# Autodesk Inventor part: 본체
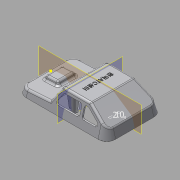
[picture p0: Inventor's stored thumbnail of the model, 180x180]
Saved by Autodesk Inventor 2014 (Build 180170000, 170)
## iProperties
Created: 2015-05
Part Number: 본체
Material: ABS 플라스틱
Document SubType Name: Modeling
Designer: Administrator
Density: 1.06 g/cm^3
Appearance: 매끄러움 - 흰색
Mass: 32.0436 g
Surface Area: 312.885 cm^2
Volume: 30.2298 cm^3
Author: Administrator
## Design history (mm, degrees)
sketch "스케치2"
  geometry: L1 (-49, -38)-(49, -38); L2 (61, -26)-(61, 26); L3 (49, 38)-(-49, 38); L4 (-61, 26)-(-61, -26); L5 (-61, -38)-(61, 38); L6 (61, -38)-(-61, 38); A1 r 12 centre (-49, 26) between (-49, 38) and (-61, 26); A2 r 12 centre (-49, -26) between (-61, -26) and (-49, -38); A3 r 12 centre (49, -26) between (49, -38) and (61, -26); A4 r 12 centre (49, 26) between (61, 26) and (49, 38); 1 further point
  constraints: 12 end point, 8 point on circle, 8 point on line, 8 tangent, 4 centre point, 3 equal radius, 2 midpoint, 2 parallel, 1 horizontal, 1 perpendicular
  dimensions: "d1" = 122 distance of L5.end L6.end; "d2" = 76 distance of L6.start L5.end; "d3" = 12 radius of A1
extrude "돌출1" new body sketch "스케치2" distance "d4" = 30; taper "d5" = -15 deg
sketch "스케치3"
  geometry: L1 (-61, 0)-(-49, 0) reference; L2 (49, 30)-(-49, 30) reference; L3 (-61, 30)-(-31, 30); L4 (-31, 30)-(-61, 10); L5 (-61, 10)-(-61, 30); 2 further points
  constraints: 6 end point, 1 horizontal, 1 midpoint, 1 perpendicular, 1 point on line, 1 vertical alignment
  dimensions: "d6" = 20 distance of L4.end L3.start; "d7" = 30 distance of L3.start L3.end
extrude "돌출2" cut sketch "스케치3" stored distance "d8" = 30; taper "d9" = 0 deg
sketch "스케치4"
  geometry: L1 (49, 0)-(61, 0) reference; L2 (61, 0)-(61, 8); L3 (61, 0)-(52.962, 30) reference; L4 (49, 30)-(-31, 30) reference; L5 (58.826, 8.114)-(19, 10.201); L6 (19, 10.201)-(6.628, 30); L7 (58.826, 8.114)-(58.826, 30); L8 (58.826, 30)-(6.628, 30); L9 (58.826, 8.114)-(61, 8); 1 further point
  constraints: 12 end point, 2 collinear, 2 perpendicular, 2 point on line
  dimensions: "d11" = 42 horizontal distance of L5.end L1.end; "d12" = 125 deg angle of L6 L5; "d13" = 3 deg angle of L5 L1; "d14" = 8 distance of L1.end L2.end
extrude "돌출3" cut sketch "스케치4" stored distance "d15" = 30; taper "d16" = 0 deg
sketch "스케치5"
  geometry: L1 (49, 38)-(-49, 38) reference; L2 (-61, 26)-(-61, -26) reference; L3 (-49, -38)-(49, -38) reference; L4 (61, -26)-(61, 26) reference; A1 r 12 centre (-49, 26) between (-49, 38) and (-61, 26) reference; A2 r 12 centre (-49, -26) between (-61, -26) and (-49, -38) reference; A3 r 12 centre (49, -26) between (49, -38) and (61, -26) reference; A4 r 12 centre (49, 26) between (61, 26) and (49, 38) reference; 1 further point
sketch "스케치6"
  geometry: L1 (-39.881, 9.267)-(-39.881, 61.267) reference; L2 (-31.476, 48.267)-(-11.476, 48.267); L3 (-11.476, 48.267)-(-11.476, 22.267); L4 (-11.476, 22.267)-(-31.476, 22.267); L5 (-31.476, 22.267)-(-31.476, 48.267); L6 (-31.476, 48.267)-(-11.476, 22.267); L7 (-11.476, 48.267)-(-31.476, 22.267); L8 (-42.476, 9.267)-(-42.476, 61.267) reference; 4 further points
  constraints: 12 end point, 4 midpoint, 2 parallel, 1 horizontal, 1 horizontal alignment, 1 perpendicular
  dimensions: "d17" = 20 distance of L3.end L4.end; "d18" = 26 distance of L2.end L3.end; "d19" = 11 distance between parallel lines of L8 L5
extrude "돌출4" join sketch "스케치6" distance "d20" = 5; taper "d21" = -20 deg
fillet "모깎기1" dims "d22" = 3
fillet "모깎기2" dims "d23" = 3
sketch "스케치7"
  geometry: 1 further point
sketch "스케치8"
  geometry: L1 (-50.664, 16.891)-(-31.756, 29.496) reference; L2 (-61, 0)-(-58.03, 11.082) reference; 1 further point
feature "쉘1" dims "d24" = 2
sketch "스케치9"
  geometry: L1 (-58.929, -26)-(-58.929, 26) reference; L2 (-49, 35.929)-(49, 35.929) reference; L3 (58.929, 26)-(58.929, -26) reference; L4 (49, -35.929)-(-49, -35.929) reference; L5 (49, 35.882)-(-49, 35.882); L6 (-58.882, 26)-(-58.882, -26); L7 (-49, -35.882)-(49, -35.882); L8 (58.882, -26)-(58.882, 26); L9 (49, 36.929)-(-49, 36.929); L10 (-59.929, 26)-(-59.929, -26); L11 (-49, -36.929)-(49, -36.929); L12 (59.929, -26)-(59.929, 26); A1 r 9.929 centre (-49, -26) between (-58.929, -26) and (-49, -35.929) reference; A2 r 9.929 centre (-49, 26) between (-49, 35.929) and (-58.929, 26) reference; A3 r 9.929 centre (49, 26) between (58.929, 26) and (49, 35.929) reference; A4 r 9.929 centre (49, -26) between (49, -35.929) and (58.929, -26) reference; A5 r 9.882 centre (-49, 26) between (-49, 35.882) and (-58.882, 26); A6 r 9.882 centre (-49, -26) between (-58.882, -26) and (-49, -35.882); A7 r 9.882 centre (49, -26) between (49, -35.882) and (58.882, -26); A8 r 9.882 centre (49, 26) between (58.882, 26) and (49, 35.882); A9 r 10.929 centre (-49, 26) between (-49, 36.929) and (-59.929, 26); A10 r 10.929 centre (-49, -26) between (-59.929, -26) and (-49, -36.929); A11 r 10.929 centre (49, -26) between (49, -36.929) and (59.929, -26); A12 r 10.929 centre (49, 26) between (59.929, 26) and (49, 36.929); 1 further point
  constraints: 16 end point, 16 point on circle, 8 centre point, 14 other
  dimensions: "d25" = 1 distance between parallel lines of L9 L2
extrude "돌출5" join sketch "스케치9" distance "d26" = 1; taper "d27" = 0 deg
sketch "스케치10"
  geometry: L1 (4.965, 30)-(-30.092, 30) reference; L2 (19, 10.201)-(7.51, 28.59) reference; L3 (-30.646, 27.832)-(-49.555, 15.226) reference; L4 (10.362, 14.59)-(4.738, 23.59); L5 (-30.242, 24.496)-(-43.742, 15.496); L6 (-31.756, 29.496)-(-50.664, 16.891) reference; L7 (-42.078, 10)-(-26.986, 10); L8 (-23.986, 13)-(-23.986, 22); L9 (-20.77, 22)-(-20.77, 13); L10 (-17.77, 10)-(7.818, 10); L11 (2.194, 25)-(-17.77, 25); L12 (-26.986, 25)-(-28.578, 25); A1 r 3 centre (-28.578, 22) between (-28.578, 25) and (-30.242, 24.496); A2 r 3 centre (-42.078, 13) between (-43.742, 15.496) and (-42.078, 10); A3 r 3 centre (-26.986, 13) between (-26.986, 10) and (-23.986, 13); A4 r 3 centre (-26.986, 22) between (-23.986, 22) and (-26.986, 25); A5 r 3 centre (-17.77, 22) between (-17.77, 25) and (-20.77, 22); A6 r 3 centre (-17.77, 13) between (-20.77, 13) and (-17.77, 10); A7 r 3 centre (2.194, 22) between (4.738, 23.59) and (2.194, 25); A8 r 3 centre (7.818, 13) between (7.818, 10) and (10.362, 14.59); 7 further points
  constraints: 16 end point, 16 point on circle, 16 tangent, 12 point on line, 8 centre point, 7 equal radius, 7 parallel, 2 perpendicular
  dimensions: "d29" = 5 distance between parallel lines of L2 L4; "d30" = 5 distance between parallel lines of L6 L5; "d31" = 28 distance of point (-51.986, 10) point (-23.986, 10); "d32" = 15 distance of point (-23.986, 10) point (-23.986, 25); "d33" = 15 distance of point (-20.77, 25) point (-20.77, 10); "d34" = 5 distance between parallel lines of L1 L11; "d35" = 5 distance between parallel lines of L1 L12; "d36" = 34 distance of point (-20.77, 10) point (13.23, 10); "d37" = 3 radius of A1
extrude "돌출6" cut sketch "스케치10" stored distance "d38" = 1; taper "d39" = 0 deg
node "작업 평면1"
sketch "스케치11"
  geometry: A1 r 4 centre (-10, 0) between (-6, 0) and (-14, 0); A2 r 4 centre (10, 0) between (14, 0) and (6, 0); A3 r 4 centre (21, 0) between (25, 0) and (17, 0); A4 r 4 centre (-21, 0) between (-17, 0) and (-25, 0); 3 further points
  constraints: 8 point on circle, 4 centre point, 13 other
  dimensions: "d41" = 8 diameter of A1; "d42" = 8 diameter of A2; "d43" = 8 diameter of A4; "d44" = 8 diameter of A3; "d45" = 20 distance of A2.centre A1.centre; "d46" = 11 distance of A1.centre A4.centre; "d47" = 11 distance of A3.centre A2.centre; "d48" = 10 distance of A2.centre point (0, 0)
extrude "돌출7" join sketch "스케치11" stored distance "d49" = 2; taper "d50" = 0 deg
chamfer "모따기1" distance "d51" = 1; stored, may be unused: second distance "d52" = 2, angle "d53" = 45 deg
sketch "스케치12"
  geometry: C1 r 3 at (0, 22); C2 r 3 at (0, -22); C3 r 3 at (40, 0); C4 r 3 at (-40, 0); 1 further point
  constraints: 4 centre point, 2 horizontal alignment, 2 vertical alignment
  dimensions: "d54" = 6 diameter of C4; "d55" = 6 diameter of C1; "d56" = 6 diameter of C3; "d57" = 6 diameter of C2; "d58" = 44 distance of C2.centre C1.centre; "d59" = 22 distance of point (0, 0) C1.centre; "d60" = 40 distance of C4.centre point (0, 0); "d61" = 40 distance of C3.centre point (0, 0)
extrude "돌출8" join sketch "스케치12" stored distance "d62" = 1; taper "d63" = 2 deg
sketch "스케치13"
  geometry: L1 (-5, -1)-(5, -1); L2 (5, -1)-(5, 1); L3 (5, 1)-(-5, 1); L4 (-5, 1)-(-5, -1); L5 (-5, -1)-(5, 1); L6 (5, -1)-(-5, 1); L7 (-5, 43)-(5, 43); L8 (5, 43)-(5, 45); L9 (5, 45)-(-5, 45); L10 (-5, 45)-(-5, 43); L11 (-5, 43)-(5, 45); L12 (5, 43)-(-5, 45); L13 (35, 21)-(45, 21); L14 (45, 21)-(45, 23); L15 (45, 23)-(35, 23); L16 (35, 23)-(35, 21); L17 (35, 21)-(45, 23); L18 (45, 21)-(35, 23); L19 (-45, 21)-(-35, 21); L20 (-35, 21)-(-35, 23); L21 (-35, 23)-(-45, 23); L22 (-45, 23)-(-45, 21); L23 (-45, 21)-(-35, 23); L24 (-35, 21)-(-45, 23); C1 r 3 at (0, 0) reference; C2 r 3 at (-40, 22) reference; C3 r 3 at (0, 44) reference; C4 r 3 at (40, 22) reference; 1 further point
  constraints: 48 end point, 8 midpoint, 8 parallel, 4 horizontal, 4 perpendicular
  dimensions: "d64" = 2 distance of L19.end L20.end; "d65" = 10 distance of L19.start L19.end; "d66" = 10 distance of L7.start L7.end; "d67" = 10 distance of L2.end L3.end; "d68" = 10 distance of L14.end L15.end; "d69" = 2 distance of L15.end L13.start; "d70" = 2 distance of L7.end L8.end; "d71" = 2 distance of L1.end L2.end
extrude "돌출9" join sketch "스케치13" stored distance "d72" = 0; taper "d73" = 0 deg
sketch "스케치14"
  geometry: L1 (2.172, 0)-(2.172, 28) reference; L2 (-7.828, 0)-(-7.828, 27.999) reference; L3 (-7.794, 28)-(27.263, 28) reference; L4 (2.172, 0)-(7.109, 28); L5 (2.172, 0)-(2.172, 28); L6 (7.109, 28)-(2.172, 28); 1 further point
  constraints: 6 end point, 2 collinear, 1 point on line
  dimensions: "d74" = 10 deg angle of L4 L5
extrude "돌출10" join sketch "스케치14" stored distance "d75" = 1; taper "d76" = 0 deg
sketch "스케치15"
  geometry: L1 (-4.519, -2.57)-(-2.913, 0) reference; L2 (-4.519, -2.57)-(-4.972, 0) reference; L3 (-4.972, 0)-(-2.913, 0) reference; 1 further point
extrude "돌출11" cut sketch "스케치15" stored distance "d77" = 1; taper "d78" = 0 deg
sketch "스케치16"
  geometry: L1 (2.172, 0)-(2.172, 12.367) reference; L2 (2.172, 0)-(6.673, 12.367); L3 (6.673, 12.367)-(2.172, 12.367); L4 (2.172, 0)-(2.172, 12.367); 1 further point
  constraints: 6 end point, 1 collinear, 1 perpendicular
  dimensions: "d79" = 20 deg angle of L2 L4
extrude "돌출12" join sketch "스케치16" stored distance "d80" = 1; taper "d81" = 0 deg
sketch "스케치17"
  geometry: L1 (6.178, 11.009)-(6.673, 12.367) reference; L2 (6.673, 12.367)-(5.537, 12.367) reference; L3 (5.89, 11.534)-(5.537, 12.367) reference; A1 r 3 centre (8.652, 12.706) between (5.89, 11.534) and (6.178, 11.009) reference; 1 further point
extrude "돌출13" cut sketch "스케치17" stored distance "d82" = 1; taper "d83" = 0 deg
sketch "스케치18"
  geometry: L1 (0, 0)-(0, 11.843) reference; L2 (-2.906, 9.978)-(-2.579, 11.049) reference; L3 (-1.675, 11.755)-(10.467, 12.391) reference; L4 (0, 0)-(-3.295, 9.052); A1 r 1 centre (-1.623, 10.756) between (-1.675, 11.755) and (-2.579, 11.049) reference; A2 r 5 centre (-7.688, 11.44) between (-7.426, 6.447) and (-2.906, 9.978) reference; 1 further point
  constraints: 2 end point, 1 point on circle
  dimensions: "d84" = 20 deg angle of L1 L4
extrude "돌출14" join sketch "스케치18" stored distance "d85" = 1; taper "d86" = 0 deg
sketch "스케치19"
  geometry: L1 (0, 0)-(0, 24.93) reference; L2 (-4.354, 27.832)-(14.555, 15.226) reference; L3 (-39.965, 28)-(-4.908, 28) reference; L4 (0, 0)-(-5.745, 28); A1 r 1 centre (-4.908, 27) between (-4.354, 27.832) and (-4.908, 28) reference; 1 further point
  constraints: 2 end point, 1 point on line
  dimensions: "d87" = 11.5941 deg angle of L1 L4
extrude "돌출15" join sketch "스케치19" stored distance "d88" = 1; taper "d89" = 0 deg
sketch "스케치20"
  geometry: L1 (2.172, 0)-(2.172, 18.263) reference; L2 (-12.182, 27.832)-(6.726, 15.226) reference; L3 (2.172, 0)-(7.521, 14.697); L4 (6.726, 15.226)-(7.521, 14.697); 1 further point
  constraints: 4 end point, 1 collinear, 1 point on line
  dimensions: "d90" = 20 deg angle of L3 L1
extrude "돌출16" join sketch "스케치20" stored distance "d91" = 1; taper "d92" = 0 deg
sketch "스케치21"
  geometry: L1 (-2.828, 23)-(-5, 23) reference; L2 (-5, 23)-(-5, 21) reference; L3 (-5, 21)-(-2.828, 21) reference; L4 (2.828, 21)-(5, 21) reference; L5 (5, 21)-(5, 23) reference; L6 (5, 23)-(2.828, 23) reference; L7 (-42.828, 1)-(-45, 1) reference; L8 (-45, 1)-(-45, -1) reference; L9 (-45, -1)-(-42.828, -1) reference; L10 (-37.172, -1)-(-35, -1) reference; L11 (-35, -1)-(-35, 1) reference; L12 (-35, 1)-(-37.172, 1) reference; L13 (37.172, 1)-(35, 1) reference; L14 (35, 1)-(35, -1) reference; L15 (35, -1)-(37.172, -1) reference; L16 (42.828, -1)-(45, -1) reference; L17 (45, -1)-(45, 1) reference; L18 (45, 1)-(42.828, 1) reference; C1 r 3 at (0, -22); C2 r 3 at (0, 22); C3 r 3 at (40, 0); A1 r 3 centre (0, -22) between (2.828, -21) and (-2.828, -21) reference; A2 r 3 centre (0, -22) between (-2.828, -23) and (2.828, -23) reference; A3 r 3 centre (0, 22) between (2.828, 23) and (-2.828, 23) reference; A4 r 3 centre (0, 22) between (-2.828, 21) and (2.828, 21) reference; A5 r 3 centre (-40, 0) between (-37.172, 1) and (-42.828, 1) reference; A6 r 3 centre (-40, 0) between (-42.828, -1) and (-37.172, -1) reference; A7 r 3 centre (40, 0) between (42.828, 1) and (37.172, 1) reference; A8 r 3 centre (40, 0) between (37.172, -1) and (42.828, -1) reference; 1 further point
  constraints: 3 centre point, 3 coincident, 3 concentric
  node "투영된 루프4"
  node "투영된 루프5"
  node "투영된 루프6"
sketch "스케치22"
  geometry: L1 (-42.828, 1)-(-45, 1) reference; L2 (-45, 1)-(-45, -1) reference; L3 (-45, -1)-(-42.828, -1) reference; L4 (-37.172, -1)-(-35, -1) reference; L5 (-35, -1)-(-35, 1) reference; L6 (-35, 1)-(-37.172, 1) reference; A1 r 3 centre (-40, 0) between (-37.172, 1) and (-42.828, 1) reference; A2 r 3 centre (-40, 0) between (-42.828, -1) and (-37.172, -1) reference; 1 further point
sketch "스케치23"
  geometry: L1 (-42.828, 1)-(-45, 1) reference; L2 (-45, 1)-(-45, -1) reference; L3 (-45, -1)-(-42.828, -1) reference; L4 (-37.172, -1)-(-35, -1) reference; L5 (-35, -1)-(-35, 1) reference; L6 (-35, 1)-(-37.172, 1) reference; C1 r 3 at (-40, 0); A1 r 3 centre (-40, 0) between (-37.172, 1) and (-42.828, 1) reference; A2 r 3 centre (-40, 0) between (-42.828, -1) and (-37.172, -1) reference; 1 further point
  constraints: 1 centre point, 1 coincident, 1 concentric
sketch "스케치24"
  geometry: L1 (2.172, 0)-(0, 0) reference; L2 (2.172, 0)-(7.109, 28) reference; L3 (-7.828, 0)-(-11.793, 22.486) reference; L4 (-8.181, 2)-(2.524, 2); L5 (0, 0)-(-5.657, 0) reference; L6 (-5.657, 0)-(-5.657, 2); L7 (0, 0)-(0, 2); L8 (-8.181, 2)-(-7.828, 0); L9 (-5.657, 0)-(-7.828, 0); L10 (0, 0)-(2.172, 0); L11 (2.524, 2)-(2.172, 0); 1 further point
  constraints: 14 end point, 4 point on line, 3 collinear, 2 parallel, 2 perpendicular
  dimensions: "d93" = 2 distance between parallel lines of L5 L4
extrude "돌출17" cut sketch "스케치24" stored distance "d94" = 2; taper "d95" = 0 deg
sketch "스케치25"
  geometry: L1 (-1.675, 11.755)-(1.733, 11.933) reference; L2 (-2.906, 9.978)-(-2.579, 11.049) reference; L3 (-3.295, 9.052)-(0, 0) reference; L4 (2.172, 0)-(0, 0) reference; L5 (10, 0)-(13.239, 8.899) reference; L6 (-0.728, 2)-(10.728, 2); L7 (7.828, 0)-(2.172, 0) reference; L8 (-0.728, 2)-(0, 0); L9 (2.172, 0)-(2.098, 2); L10 (8.28, 12.277)-(10, 12.367) reference; L11 (10, 0)-(7.828, 0) reference; L12 (10, 0)-(13.239, 8.899) reference; L13 (11.44, 11.783)-(11.878, 10.753) reference; L14 (10.746, 12.367)-(10, 12.367) reference; L15 (0, 0)-(2.172, 0); A1 r 1 centre (-1.623, 10.756) between (-1.675, 11.755) and (-2.579, 11.049) reference; A2 r 5 centre (-7.688, 11.44) between (-3.295, 9.052) and (-2.906, 9.978) reference; A3 r 5 centre (16.48, 12.706) between (11.878, 10.753) and (13.239, 8.899) reference; A4 r 1 centre (10.52, 11.393) between (11.44, 11.783) and (10.746, 12.367) reference; 1 further point
  constraints: 8 end point, 3 point on line, 2 collinear, 1 parallel, 3 other
  dimensions: "d96" = 2 distance between parallel lines of L7 L6
sketch "스케치26"
  geometry: L1 (-1.675, 11.755)-(1.733, 11.933) reference; L2 (-2.906, 9.978)-(-2.579, 11.049) reference; L3 (-3.295, 9.052)-(0, 0) reference; L4 (2.172, 0)-(0, 0) reference; L5 (8.28, 12.277)-(10, 12.367) reference; L6 (10, 0)-(7.828, 0) reference; L7 (10, 0)-(13.239, 8.899) reference; L8 (11.44, 11.783)-(11.878, 10.753) reference; L9 (10.746, 12.367)-(10, 12.367) reference; A1 r 1 centre (-1.623, 10.756) between (-1.675, 11.755) and (-2.579, 11.049) reference; A2 r 5 centre (-7.688, 11.44) between (-3.295, 9.052) and (-2.906, 9.978) reference; A3 r 5 centre (16.48, 12.706) between (11.878, 10.753) and (13.239, 8.899) reference; A4 r 1 centre (10.52, 11.393) between (11.44, 11.783) and (10.746, 12.367) reference; 1 further point
  constraints: 2 other
sketch "스케치27"
  geometry: L1 (-1.675, 11.755)-(1.733, 11.933) reference; L2 (-2.906, 9.978)-(-2.579, 11.049) reference; L3 (-3.295, 9.052)-(0, 0) reference; L4 (2.172, 0)-(0, 0) reference; L5 (-3.295, 9.052)-(0, 0) reference; L6 (2.172, 0)-(0, 0) reference; L7 (2.172, 0)-(2.098, 2) reference; L8 (-0.728, 2)-(0, 0); L9 (2.172, 0)-(0, 0); L10 (2.172, 0)-(2.098, 2); A1 r 1 centre (-1.623, 10.756) between (-1.675, 11.755) and (-2.579, 11.049) reference; A2 r 5 centre (-7.688, 11.44) between (-3.295, 9.052) and (-2.906, 9.978) reference; 2 further points
  constraints: 6 end point, 3 collinear, 1 point on line, 1 other
sketch "스케치28"
  geometry: L1 (-5.745, 28)-(0, 0) reference; L2 (2.172, 0)-(0, 0) reference; L3 (-0.41, 2)-(2.098, 2); 2 further points
  constraints: 2 end point, 1 parallel, 1 point on line, 2 other
  dimensions: "d97" = 2 distance between parallel lines of L3 L2
extrude "돌출18" cut sketch "스케치28" stored distance "d98" = 2; taper "d99" = 0 deg
sketch "스케치29"
  geometry: L1 (2.172, 0)-(0, 0) reference; L2 (2.172, 0)-(7.521, 14.697) reference; L3 (0.074, 2)-(2.9, 2); 2 further points
  constraints: 2 end point, 1 parallel, 1 point on line, 2 other
  dimensions: "d100" = 2 distance between parallel lines of L1 L3
extrude "돌출19" cut sketch "스케치29" stored distance "d101" = 2; taper "d102" = 0 deg
sketch "스케치30"
  geometry: L1 (-2.828, -21)-(-2.828, -23) reference; L2 (2.828, -23)-(2.828, -21) reference; A1 r 3 centre (0, -22) between (-2.828, -23) and (2.828, -23) reference; A2 r 3 centre (0, -22) between (2.828, -21) and (-2.828, -21) reference; 1 further point
hole "구멍1" sketch "스케치21" diameter "d103" = 3.242; stored, may be unused: countersink angle "d107" = 90 deg, drill point angle "d109" = 118 deg; dims "d104" = 9, "d105" = 4, "d106" = 2, "d108" = 11
sketch "스케치31"
  geometry: L1 (-1.675, 11.755)-(1.733, 11.933) reference; L2 (-2.906, 9.978)-(-2.579, 11.049) reference; L3 (-3.295, 9.052)-(0, 0) reference; L4 (2.172, 0)-(0, 0) reference; A1 r 1 centre (-1.623, 10.756) between (-1.675, 11.755) and (-2.579, 11.049) reference; A2 r 5 centre (-7.688, 11.44) between (-3.295, 9.052) and (-2.906, 9.978) reference; 1 further point
  constraints: 1 other
sketch "스케치32"
  geometry: L1 (-1.675, 11.755)-(1.733, 11.933) reference; L2 (-2.906, 9.978)-(-2.579, 11.049) reference; L3 (-3.295, 9.052)-(0, 0) reference; L4 (2.172, 0)-(0, 0) reference; L5 (-0.736, 2.021)-(0, 0); A1 r 1 centre (-1.623, 10.756) between (-1.675, 11.755) and (-2.579, 11.049) reference; A2 r 5 centre (-7.688, 11.44) between (-3.295, 9.052) and (-2.906, 9.978) reference; 1 further point
  constraints: 2 end point, 1 collinear, 1 point on line, 1 other
sketch "스케치33"
  geometry: L1 (2.172, 0)-(0, 0) reference; L2 (-5.657, 0)-(-7.828, 0) reference; L3 (-8.556, 2)-(-7.828, 0) reference; L4 (-8.556, 2)-(2.9, 2) reference; L5 (-5.657, 0)-(-5.731, 2) reference; 3 further points
extrude "돌출20" cut sketch "스케치33" stored distance "d110" = 2; taper "d111" = 0 deg
sketch "스케치34"
  geometry: L1 (0.451, 12.277)-(2.172, 12.367) reference; L2 (2.172, 0)-(0, 0) reference; L3 (2.172, 0)-(5.411, 8.899) reference; L4 (3.612, 11.783)-(4.049, 10.753) reference; L5 (2.917, 12.367)-(2.172, 12.367) reference; L6 (2.172, 0)-(0, 0) reference; L7 (2.172, 0)-(5.411, 8.899) reference; L8 (0, 0)-(2.172, 0); L9 (2.917, 2.048)-(2.172, 0); L10 (0, 0)-(0, 0); A1 r 5 centre (8.652, 12.706) between (4.049, 10.753) and (5.411, 8.899) reference; A2 r 1 centre (2.691, 11.393) between (3.612, 11.783) and (2.917, 12.367) reference; 1 further point
  constraints: 6 end point, 2 collinear, 1 perpendicular, 1 point on line, 2 other
sketch "스케치35"
  geometry: L1 (2.172, 12.367)-(0.451, 12.277) reference; L2 (2.917, 12.367)-(2.172, 12.367) reference; L3 (4.049, 10.753)-(3.612, 11.783) reference; L4 (2.172, 0)-(5.411, 8.899) reference; L5 (0, 0)-(2.172, 0) reference; L6 (0.073, 1.985)-(2.894, 1.985); A1 r 1 centre (2.691, 11.393) between (3.612, 11.783) and (2.917, 12.367) reference; A2 r 5 centre (8.652, 12.706) between (4.049, 10.753) and (5.411, 8.899) reference; 3 further points
  constraints: 2 end point, 1 parallel, 1 point on line, 4 other
extrude "돌출21" cut sketch "스케치35" stored distance "d112" = 2; taper "d113" = 0 deg
hole "구멍2" diameter "d116" = 3.242; stored, may be unused: countersink angle "d120" = 90 deg, drill point angle "d122" = 118 deg; dims "d114" = 10, "d115" = 10, "d117" = 9, "d118" = 4, "d119" = 2, "d121" = 11
sketch "스케치36"
  geometry: L1 (61, 26)-(61, -26) reference; 2 further points
  constraints: 1 horizontal alignment, 1 other
  dimensions: "d123" = 50 distance from line of L1 point (11, 0)
feature "엠보싱1" sketch "스케치36" dims "d124" = 0.5, "d125" = 0
sketch "스케치37"
  geometry: L1 (-45.728, 2)-(-50.349, 14.697) reference; L2 (-42.902, 2)-(-45.728, 2) reference; L3 (-45.728, 2)-(-48.217, 16.118); L4 (-31.756, 29.496)-(-50.664, 16.891) reference; L5 (-48.217, 16.118)-(-49.555, 15.226); L6 (-49.555, 15.226)-(-50.349, 14.697); 1 further point
  constraints: 6 end point, 1 parallel
  dimensions: "d126" = 100 deg angle of L2 L3; "d127" = 2 distance between parallel lines of L4 L5
extrude "돌출22" join sketch "스케치37" stored distance "d128" = 10; taper "d129" = 0 deg
sketch "스케치38"
  geometry: L1 (0, 2)-(2.826, 2) reference; L2 (0, 0)-(0, 2) reference; L3 (2.826, 0)-(0, 0) reference; L4 (2.826, 0)-(2.826, 2) reference; L5 (11.138, 2)-(11.138, 0) reference; 1 further point
sketch "스케치39"
  geometry: L1 (0, 2)-(2.826, 2) reference; L2 (0, 0)-(0, 2) reference; L3 (2.826, 0)-(0, 0) reference; L4 (2.826, 0)-(2.826, 2) reference; L5 (0.728, 2)-(10.728, 2); L6 (10.728, 2)-(10.728, 0); L7 (10.728, 0)-(0.728, 0); L8 (0.728, 0)-(0.728, 2); C1 r 1.621 at (5.728, 1) reference; 6 further points
  constraints: 8 end point, 3 coincident, 2 midpoint, 2 parallel, 1 horizontal, 1 horizontal alignment, 1 perpendicular, 1 vertical alignment
  dimensions: "d130" = 10 distance of L5.start L5.end; "d131" = 2 distance of L5.end L6.end
sketch "스케치40"
  geometry: L1 (2.826, 0)-(0, 0) reference; L2 (7.447, -12.697)-(0.631, -17.241) reference; L3 (2.826, 0)-(7.447, -12.697) reference; L4 (2.098, 0)-(-7.902, 0) reference; L5 (2.098, 0)-(2.938, -4.766); L6 (-7.902, 0)-(-10.507, -14.77); L7 (7.762, -14.891)-(-11.147, -27.496) reference; L8 (-12.811, -26)-(-47.868, -26) reference; L9 (-13.647, -26)-(-8.313, 0) reference; L10 (-12.811, -26)-(-13.647, -26); L11 (-8.313, 0)-(-7.902, 0); L12 (2.938, -4.766)-(4.664, -14.552); L13 (7.447, -12.697)-(4.664, -14.552); L14 (2.938, 0)-(2.098, 0); L15 (-10.507, -14.77)-(-12.811, -26); 2 further points
  constraints: 16 end point, 4 collinear, 1 parallel, 1 point on line, 1 other
  dimensions: "d132" = 100 deg angle of L5 L1; "d133" = 100 deg angle of L4 L6
extrude "돌출23" cut sketch "스케치40" stored distance "d134" = 10; taper "d135" = 0 deg
sketch "스케치41"
  geometry: L1 (-42.828, 1)-(-42.828, -1) reference; L2 (-37.172, -1)-(-37.172, 1) reference; C1 r 3 at (-40, 0); A1 r 3 centre (-40, 0) between (-42.828, -1) and (-37.172, -1) reference; A2 r 3 centre (-40, 0) between (-37.172, 1) and (-42.828, 1) reference; 1 further point
  constraints: 1 centre point, 1 coincident, 1 concentric
extrude "돌출24" join sketch "스케치41" distance "d136" = 2; taper "d137" = 2 deg
sketch "스케치42"
  geometry: L1 (-2.828, -21)-(-2.828, -23) reference; L2 (2.828, -23)-(2.828, -21) reference; C1 r 3 at (0, -22); A1 r 3 centre (0, -22) between (-2.828, -23) and (2.828, -23) reference; A2 r 3 centre (0, -22) between (2.828, -21) and (-2.828, -21) reference; 1 further point
  constraints: 1 centre point, 1 coincident, 1 concentric
extrude "돌출25" join sketch "스케치42" distance "d138" = 2; taper "d139" = 2 deg
node "솔리드1"
mirror "대칭1"
mirror "대칭2"
mirror "대칭3"
mirror "대칭4"
mirror "대칭5"
node "투영된 루프1"
node "투영된 루프2"
node "투영된 루프3"
node "투영된 루프7"
node "작업 평면2"
node "작업 평면3"
other parameters: "d28" = 5, "d40" = -63
